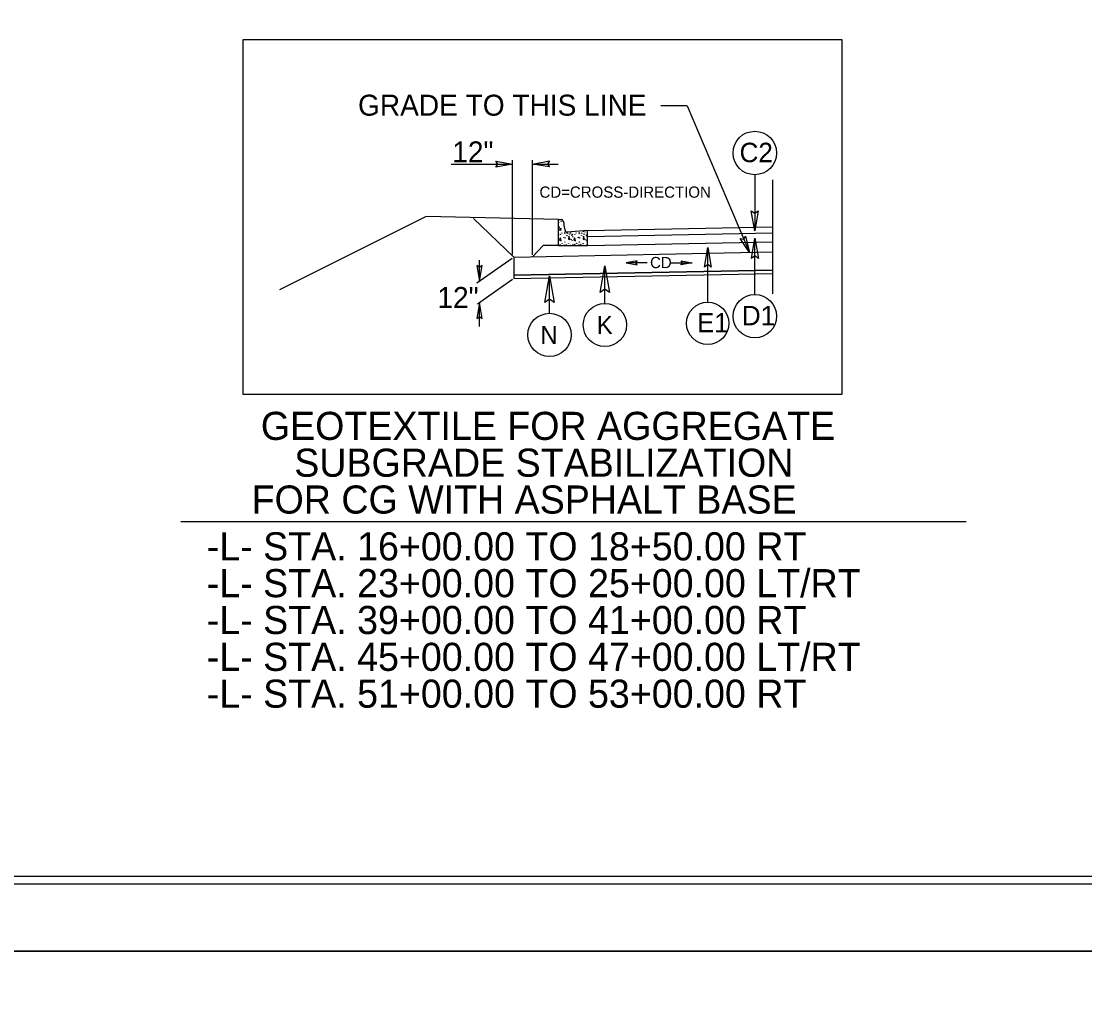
# Model space of a CAD drawing. Extents: x 1901670 to 1902225, y 193498 to 194278.
# Drawn here: x 1901993.48 to 1902028.95, y 194156.63 to 194189.05 of the extents above; entities that cross this region are included whole.
import ezdxf

# ---------------------------------------------------------------- set-up
doc = ezdxf.new("R2010")
doc.units = 0
for name, color, linetype in [('Old_Level_1', 7, 'Continuous'), ('Old_Level_11', 7, 'Continuous'), ('Old_Level_20', 7, 'Continuous'), ('Prop Dimension', 7, 'Continuous'), ('Prop Dimension Text', 7, 'Continuous'), ('Prop Lane Arrow CELL', 7, 'Continuous'), ('Prop Terminator CELL', 7, 'Continuous'), ('Sheet Border Standard 30in CELL', 7, 'Continuous'), ('Sheet Cutting Line CELL', 7, 'Continuous'), ('Sheet Plot Border Inside CELL', 7, 'Continuous'), ('Sheet Plot Border Outside CELL', 7, 'Continuous'), ('Typical Curb CELL', 7, 'Continuous'), ('Typical Hinge Slope Interstate CELL', 7, 'Continuous'), ('Typical ID Circle CELL', 7, 'Continuous'), ('Typical Pavement Slope CELL', 7, 'Continuous'), ('Typical Shoulder Slope CELL', 7, 'Continuous'), ('Typical Terminator CELL', 7, 'Continuous'), ('Typical Text General CELL', 7, 'Continuous'), ('Typical Text ID Circle CELL', 7, 'Continuous')]:
    doc.layers.add(name, color=color, linetype=linetype)

msp = doc.modelspace()

# ---------------------------------------------------------------- linework, layer by layer
at = {"layer": 'Old_Level_1'}
msp.add_line((1901998.795, 194172.349), (1902024.992, 194172.349), dxfattribs=at)
at = {"layer": 'Old_Level_11'}
for p, q in [((1902017.943, 194183.925), (1902017.943, 194182.051)), ((1902017.945, 194179.93), (1902017.945, 194181.804)), ((1902016.373, 194179.674), (1902016.373, 194181.501))]:
    msp.add_line(p, q, dxfattribs=at)
for points in [[(1902000.877, 194188.442), (1902020.842, 194188.442), (1902020.842, 194176.597), (1902000.877, 194176.597)], [(1902018.058, 194182.723), (1902017.943, 194182.051), (1902017.823, 194182.726), (1902017.943, 194182.64)], [(1902017.829, 194181.132), (1902017.945, 194181.804), (1902018.064, 194181.129), (1902017.945, 194181.214)], [(1902016.261, 194180.846), (1902016.373, 194181.501), (1902016.49, 194180.843), (1902016.373, 194180.926)]]:
    msp.add_lwpolyline(points, close=True, dxfattribs=at)
for centre, radius in [((1902017.943, 194184.65), 0.725), ((1902017.945, 194179.204), 0.725), ((1902016.373, 194178.967), 0.707)]:
    msp.add_circle(centre, radius, dxfattribs=at)
at = {"layer": 'Prop Dimension'}
for p, q in [((1902015.69, 194186.229), (1902014.814, 194186.229)), ((1902015.69, 194186.229), (1902017.767, 194181.331)), ((1902018.543, 194179.951), (1902018.543, 194183.756)), ((1902014.359, 194180.989), (1902013.649, 194180.989)), ((1902015.146, 194180.989), (1902015.856, 194180.989))]:
    msp.add_line(p, q, dxfattribs=at)
at = {"layer": 'Prop Dimension Text'}
for p, q in [((1902009.866, 194181.266), (1902009.866, 194184.416)), ((1902010.531, 194181.266), (1902010.531, 194184.416)), ((1902007.818, 194184.282), (1902009.866, 194184.282)), ((1902010.531, 194184.282), (1902011.39, 194184.282)), ((1902010.531, 194181.248), (1902010.531, 194184.202)), ((1902009.849, 194181.133), (1902008.675, 194180.311)), ((1902008.758, 194180.369), (1902008.758, 194181.076)), ((1902009.863, 194180.43), (1902008.693, 194179.611)), ((1902008.76, 194178.856), (1902008.76, 194179.658))]:
    msp.add_line(p, q, dxfattribs=at)
at = {"layer": 'Prop Terminator CELL'}
for points in [[(1902009.304, 194184.377), (1902009.866, 194184.282), (1902009.301, 194184.18), (1902009.373, 194184.281)], [(1902011.093, 194184.187), (1902010.531, 194184.282), (1902011.095, 194184.384), (1902011.024, 194184.283)], [(1902008.668, 194180.896), (1902008.758, 194180.369), (1902008.852, 194180.899), (1902008.758, 194180.831)], [(1902014.023, 194181.053), (1902013.649, 194180.989), (1902014.025, 194180.922), (1902013.977, 194180.989)], [(1902015.482, 194181.053), (1902015.856, 194180.989), (1902015.48, 194180.922), (1902015.528, 194180.989)], [(1902008.851, 194179.132), (1902008.76, 194179.658), (1902008.667, 194179.129), (1902008.76, 194179.196)]]:
    msp.add_lwpolyline(points, close=True, dxfattribs=at)
at = {"layer": 'Sheet Border Standard 30in CELL'}
msp.add_lwpolyline([(1902132.544, 194265.514), (1901982.544, 194265.514), (1901982.544, 194160.514), (1902132.544, 194160.514)], close=True, dxfattribs=at)
at = {"layer": 'Sheet Cutting Line CELL'}
for p, q in [((1902134.244, 194158.014), (1901965.844, 194158.014)), ((1901965.844, 194158.014), (1902134.244, 194158.014))]:
    msp.add_line(p, q, dxfattribs=at)
at = {"layer": 'Sheet Plot Border Inside CELL'}
msp.add_lwpolyline([(1902133.794, 194265.769), (1901967.144, 194265.769), (1901967.144, 194160.259), (1902133.794, 194160.259)], close=True, dxfattribs=at)
at = {"layer": 'Sheet Plot Border Outside CELL'}
for points in [[(1902134.244, 194268.014), (1901965.844, 194268.014), (1901965.844, 194158.014), (1902134.244, 194158.014)], [(1902134.244, 194158.014), (1901965.844, 194158.014), (1901965.844, 194048.014), (1902134.244, 194048.014)]]:
    msp.add_lwpolyline(points, close=True, dxfattribs=at)
at = {"layer": 'Typical Curb CELL'}
for p, q in [((1902011.396, 194181.56), (1902011.396, 194182.429)), ((1902011.396, 194182.429), (1902011.496, 194182.429)), ((1902011.41, 194182.101), (1902011.469, 194182.14)), ((1902011.463, 194182.061), (1902011.41, 194182.101)), ((1902011.469, 194182.14), (1902011.463, 194182.061)), ((1902011.589, 194182.212), (1902011.589, 194182.221)), ((1902012.362, 194182.067), (1902011.685, 194182.004)), ((1902011.745, 194181.872), (1902011.732, 194181.774)), ((1902011.778, 194181.768), (1902011.745, 194181.872)), ((1902012.228, 194181.872), (1902012.214, 194181.774)), ((1902012.261, 194181.768), (1902012.228, 194181.872)), ((1902012.362, 194181.56), (1902012.362, 194182.067)), ((1902011.396, 194181.56), (1902012.362, 194181.56)), ((1902011.458, 194181.824), (1902011.419, 194181.758)), ((1902011.419, 194181.758), (1902011.483, 194181.724)), ((1902011.483, 194181.724), (1902011.458, 194181.824)), ((1902011.732, 194181.774), (1902011.778, 194181.768)), ((1902011.941, 194181.824), (1902011.901, 194181.758)), ((1902011.901, 194181.758), (1902011.965, 194181.724)), ((1902011.965, 194181.724), (1902011.941, 194181.824)), ((1902012.214, 194181.774), (1902012.261, 194181.768))]:
    msp.add_line(p, q, dxfattribs=at)
for centre in [(1902011.401, 194182.334), (1902011.485, 194182.363), (1902011.421, 194182.175), (1902011.458, 194181.937), (1902011.505, 194181.981), (1902011.604, 194182.006), (1902011.61, 194181.962), (1902011.679, 194181.888), (1902011.69, 194181.976), (1902011.765, 194181.942), (1902011.802, 194181.98), (1902011.844, 194181.908), (1902011.866, 194181.937), (1902011.941, 194181.937), (1902011.987, 194181.981), (1902012.087, 194182.006), (1902012.093, 194181.962), (1902012.161, 194181.888), (1902012.172, 194181.976), (1902012.23, 194182.031), (1902012.248, 194181.942), (1902012.285, 194182.016), (1902012.327, 194181.908), (1902012.349, 194181.937), (1902011.452, 194181.6), (1902011.518, 194181.635), (1902011.573, 194181.838), (1902011.586, 194181.58), (1902011.608, 194181.679), (1902011.621, 194181.813), (1902011.652, 194181.605), (1902011.732, 194181.625), (1902011.793, 194181.565), (1902011.813, 194181.769), (1902011.85, 194181.729), (1902011.872, 194181.853), (1902011.875, 194181.585), (1902011.934, 194181.6), (1902012, 194181.635), (1902012.056, 194181.838), (1902012.069, 194181.58), (1902012.091, 194181.679), (1902012.104, 194181.813), (1902012.135, 194181.605), (1902012.214, 194181.625), (1902012.276, 194181.565), (1902012.296, 194181.769), (1902012.333, 194181.729), (1902012.355, 194181.853), (1902012.357, 194181.585)]:
    msp.add_ellipse(centre, major_axis=(0, 0.00697), ratio=0.444444, dxfattribs=at)
for centre, major_axis, end_param in [((1902011.496, 194182.221), (0, 0.208), 6.283185), ((1902011.681, 194182.212), (0, -0.208), 6.324802)]:
    msp.add_ellipse(centre, major_axis=major_axis, ratio=0.444444, start_param=4.712389, end_param=end_param, dxfattribs=at)
at = {"layer": 'Typical Hinge Slope Interstate CELL'}
msp.add_line((1902006.986, 194182.536), (1902002.087, 194180.086), dxfattribs=at)
msp.add_lwpolyline([(1902018.541, 194180.741), (1902009.905, 194180.569), (1902009.907, 194180.461), (1902018.543, 194180.634)], close=True, dxfattribs=at)
at = {"layer": 'Typical ID Circle CELL'}
for p, q in [((1902012.942, 194179.633), (1902012.942, 194180.887)), ((1902011.096, 194179.301), (1902011.096, 194180.556))]:
    msp.add_line(p, q, dxfattribs=at)
for centre in [(1902012.942, 194178.911), (1902011.096, 194178.58)]:
    msp.add_circle(centre, 0.721, dxfattribs=at)
at = {"layer": 'Typical Pavement Slope CELL'}
for p, q in [((1902012.362, 194182.067), (1902018.543, 194182.191)), ((1902012.362, 194181.861), (1902018.547, 194181.985)), ((1902012.362, 194181.562), (1902018.553, 194181.686)), ((1902009.907, 194181.174), (1902018.543, 194181.347)), ((1902009.905, 194180.569), (1902018.541, 194180.741))]:
    msp.add_line(p, q, dxfattribs=at)
at = {"layer": 'Typical Shoulder Slope CELL'}
for p, q in [((1902011.396, 194182.429), (1902006.986, 194182.536)), ((1902008.558, 194182.47), (1902009.907, 194181.174)), ((1902010.531, 194181.187), (1902010.89, 194181.56)), ((1902011.396, 194181.56), (1902010.89, 194181.56)), ((1902009.907, 194181.174), (1902009.907, 194180.569)), ((1902009.907, 194180.461), (1902018.543, 194180.634))]:
    msp.add_line(p, q, dxfattribs=at)
at = {"layer": 'Typical Terminator CELL'}
for points in [[(1902017.636, 194181.87), (1902017.767, 194181.331), (1902017.459, 194181.797), (1902017.576, 194181.772)], [(1902012.789, 194179.997), (1902012.942, 194180.887), (1902013.101, 194179.992), (1902012.942, 194180.106)], [(1902010.943, 194179.665), (1902011.096, 194180.556), (1902011.255, 194179.66), (1902011.096, 194179.774)]]:
    msp.add_lwpolyline(points, close=True, dxfattribs=at)

# ---------------------------------------------------------------- texts
at = {"layer": 'Old_Level_20'}
for s, height, p in [('C2', 0.6491, (1902017.436, 194184.344)), ('D1', 0.6491, (1902017.512, 194178.901)), ('E1', 0.6396, (1902016.019, 194178.668))]:
    msp.add_text(s, height=height, dxfattribs=at).set_placement(p)
at = {"layer": 'Prop Dimension Text'}
for p in [(1902007.853, 194184.337), (1902007.357, 194179.479)]:
    msp.add_text('12"', height=0.7, dxfattribs=at).set_placement(p)
at = {"layer": 'Prop Lane Arrow CELL'}
for s, p in [('-L- STA. 16+00.00 TO 18+50.00 RT', (1901999.664, 194171.056)), ('-L- STA. 23+00.00 TO 25+00.00 LT/RT', (1901999.664, 194169.827)), ('-L- STA. 39+00.00 TO 41+00.00 RT', (1901999.664, 194168.598)), ('-L- STA. 45+00.00 TO 47+00.00 LT/RT', (1901999.664, 194167.369)), ('-L- STA. 51+00.00 TO 53+00.00 RT', (1901999.664, 194166.14))]:
    msp.add_text(s, height=0.9375, dxfattribs=at).set_placement(p)
at = {"layer": 'Typical Hinge Slope Interstate CELL'}
for s, height, p in [('CD=CROSS-DIRECTION', 0.37433, (1902010.762, 194183.158)), ('CD', 0.3743, (1902014.449, 194180.808))]:
    msp.add_text(s, height=height, dxfattribs=at).set_placement(p)
at = {"layer": 'Typical Text General CELL'}
for s, height, p in [('GRADE TO THIS LINE', 0.7, (1902004.71, 194185.896)), ('GEOTEXTILE FOR AGGREGATE ', 0.9375, (1902001.467, 194175.076)), ('SUBGRADE STABILIZATION ', 0.9375, (1902002.582, 194173.847)), ('FOR CG WITH ASPHALT BASE', 0.9375, (1902001.159, 194172.618))]:
    msp.add_text(s, height=height, dxfattribs=at).set_placement(p)
at = {"layer": 'Typical Text ID Circle CELL'}
for s, p in [('K', (1902012.67, 194178.611)), ('N', (1902010.789, 194178.28))]:
    msp.add_text(s, height=0.6, rotation=360, dxfattribs=at).set_placement(p)

doc.saveas('drawing.dxf')
